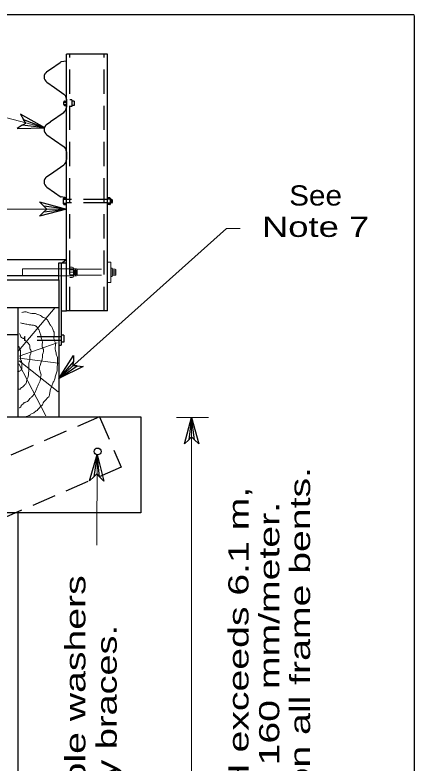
# Model space of a CAD drawing. Extents: x 13426 to 15509, y -9298 to -5111.
# Drawn here: x 15483.31 to 15509.15, y -5428.19 to -5379.81 of the extents above; entities that cross this region are included whole.
import ezdxf
from ezdxf.enums import TextEntityAlignment as Align

# ---------------------------------------------------------------- set-up
doc = ezdxf.new("R2010")
doc.units = 0
doc.header["$LTSCALE"] = 0.52
doc.linetypes.add('MEDIUM_DASHED', pattern=[4.5, 3, -1.5])
for name, color, linetype, lineweight in [('1', 7, 'Continuous', 13), ('15', 7, 'Continuous', 13), ('16', 7, 'Continuous', 25), ('2', 7, 'Continuous', 25), ('20', 7, 'Continuous', 13), ('3', 7, 'Continuous', 25), ('30', 7, 'Continuous', 25), ('4', 7, 'Continuous', 13), ('5', 7, 'Continuous', 25)]:
    doc.layers.add(name, color=color, linetype=linetype, lineweight=lineweight)
doc.layers.add('19', color=7, linetype='Continuous')

msp = doc.modelspace()

# ---------------------------------------------------------------- linework, layer by layer
at = {"layer": '1', "lineweight": 25}
for p, q in [((15485.605, -5383.316), (15486.228, -5382.877)), ((15486.643, -5382.787), (15486.296, -5382.848)), ((15485.375, -5383.473), (15485.603, -5383.314)), ((15485.375, -5384.161), (15485.878, -5384.508)), ((15485.877, -5384.508), (15486.465, -5384.922)), ((15486.643, -5385.768), (15486.643, -5385.265)), ((15486.643, -5385.265), (15486.643, -5385.768)), ((15485.601, -5386.709), (15486.489, -5386.094)), ((15485.375, -5386.873), (15485.603, -5386.713)), ((15485.375, -5387.555), (15485.877, -5387.906)), ((15485.877, -5387.904), (15486.489, -5388.332)), ((15486.643, -5388.656), (15486.643, -5389.155)), ((15486.643, -5389.155), (15486.643, -5388.656)), ((15485.375, -5390.948), (15485.877, -5391.3)), ((15485.877, -5391.299), (15486.228, -5391.548)), ((15486.642, -5391.635), (15486.295, -5391.576)), ((15363.992, -5405.801), (15491.456, -5405.801)), ((15491.456, -5405.801), (15491.456, -5411.997)), ((15491.456, -5411.997), (15381.02, -5411.997)), ((15483.489, -5411.997), (15483.489, -5456.247))]:
    msp.add_line(p, q, dxfattribs=at)
msp.add_lwpolyline([(15485.375, -5390.265), (15485.603, -5390.106), (15486.465, -5389.503)], dxfattribs=at)
for centre, radius, start, end in [((15486.3263, -5383.0135), 0.1669, 100.00085, 124.99926), ((15485.6148, -5383.8174), 0.4173, 124.98392, 235.01553), ((15486.2269, -5385.2642), 0.4173, 359.99953, 55.01553), ((15486.2269, -5385.765), 0.4173, 304.98447, 0.00048), ((15485.6148, -5387.2117), 0.4173, 124.98392, 235.01552), ((15485.6148, -5387.2118), 0.4173, 124.98445, 235.01605), ((15486.2269, -5388.6585), 0.4173, 359.99946, 55.01547), ((15486.2269, -5389.1593), 0.4173, 304.98441, 0.00041), ((15485.6148, -5390.6061), 0.4173, 124.98445, 235.01605), ((15486.324, -5391.4111), 0.1669, 235.00071, 259.99912)]:
    msp.add_arc(centre, radius, start, end, dxfattribs=at)
at = {"layer": '15', "lineweight": 25}
for p, q in [((15486.475, -5385.44), (15486.643, -5385.44)), ((15486.475, -5385.59), (15486.643, -5385.59)), ((15486.519, -5385.378), (15486.643, -5385.378)), ((15486.519, -5385.654), (15486.643, -5385.654))]:
    msp.add_line(p, q, dxfattribs=at)
at = {"layer": '15', "linetype": 'MEDIUM_DASHED', "lineweight": 25}
for p, q in [((15487.138, -5385.378), (15486.996, -5385.378)), ((15487.138, -5385.655), (15486.996, -5385.655))]:
    msp.add_line(p, q, dxfattribs=at)
at = {"layer": '15'}
for p, q in [((15486.643, -5392.358), (15368.805, -5392.358)), ((15496.999, -5393.623), (15486.145, -5403.326)), ((15497.881, -5393.623), (15496.999, -5393.623)), ((15495.847, -5405.842), (15493.759, -5405.842)), ((15494.748, -5405.842), (15494.748, -5464.202)), ((15488.612, -5414.097), (15488.623, -5408.393))]:
    msp.add_line(p, q, dxfattribs=at)
msp.add_lwpolyline([(15485.245, -5387.109), (15480.713, -5385.917), (15478, -5385.917)], dxfattribs=at)
at = {"layer": '16'}
for points in [[(15483.778, -5386.94), (15483.447, -5387.148), (15485.245, -5387.109), (15483.676, -5386.23), (15483.87, -5386.569), (15485.245, -5387.109), (15483.778, -5386.94), (15484.01, -5386.801), (15483.87, -5386.569)], [(15485.178, -5392.166), (15484.908, -5391.885), (15486.643, -5392.358), (15484.908, -5392.831), (15485.178, -5392.55), (15486.643, -5392.358), (15485.178, -5392.166), (15485.37, -5392.358), (15485.178, -5392.55)], [(15487.344, -5402.507), (15487.726, -5402.536), (15486.145, -5403.326), (15487.107, -5401.843), (15487.093, -5402.226), (15486.145, -5403.326), (15487.344, -5402.507), (15487.078, -5402.492), (15487.093, -5402.226)], [(15494.56, -5407.281), (15494.283, -5407.546), (15494.748, -5405.842), (15495.213, -5407.546), (15494.936, -5407.281), (15494.748, -5405.842), (15494.56, -5407.281), (15494.748, -5407.093), (15494.936, -5407.281)], [(15488.41, -5409.67), (15488.127, -5409.929), (15488.63, -5408.236), (15489.057, -5409.95), (15488.786, -5409.678), (15488.63, -5408.236), (15488.41, -5409.67), (15488.602, -5409.486), (15488.786, -5409.678)]]:
    msp.add_lwpolyline(points, dxfattribs=at)
at = {"layer": '2'}
for p, q in [((15486.478, -5400.523), (15486.311, -5400.523)), ((15486.478, -5400.523), (15486.478, -5400.966)), ((15486.478, -5400.966), (15486.311, -5400.966))]:
    msp.add_line(p, q, dxfattribs=at)
at = {"layer": '2', "linetype": 'MEDIUM_DASHED'}
for p, q in [((15486.311, -5400.855), (15483.932, -5400.855)), ((15488.78, -5405.801), (15474.434, -5411.997)), ((15488.78, -5405.801), (15490.184, -5409.051)), ((15490.184, -5409.051), (15478.179, -5414.237))]:
    msp.add_line(p, q, dxfattribs=at)
msp.add_lwpolyline([(15486.311, -5400.634), (15483.932, -5400.634), (15483.932, -5400.855)], dxfattribs=at)
at = {"layer": '2'}
msp.add_circle((15488.6628, -5408.0385), 0.2213, dxfattribs=at)
at = {"layer": '3'}
for p, q in [((15486.475, -5385.61), (15486.475, -5385.422)), ((15486.452, -5392.029), (15486.452, -5391.68)), ((15486.452, -5391.732), (15486.643, -5391.732)), ((15486.496, -5391.636), (15486.642, -5391.636)), ((15489.488, -5391.732), (15489.298, -5391.732)), ((15489.444, -5391.636), (15489.299, -5391.636)), ((15489.488, -5392.029), (15489.488, -5391.68)), ((15489.573, -5391.744), (15489.49, -5391.744)), ((15489.573, -5391.966), (15489.49, -5391.966)), ((15489.517, -5391.776), (15489.517, -5391.936)), ((15489.564, -5391.776), (15489.564, -5391.936)), ((15489.618, -5391.922), (15489.618, -5391.789)), ((15486.452, -5391.981), (15486.643, -5391.981)), ((15486.496, -5392.074), (15486.642, -5392.074)), ((15489.488, -5391.981), (15489.298, -5391.981)), ((15489.444, -5392.074), (15489.299, -5392.074))]:
    msp.add_line(p, q, dxfattribs=at)
at = {"layer": '3', "linetype": 'MEDIUM_DASHED'}
for p, q in [((15486.996, -5385.293), (15486.865, -5385.293)), ((15486.996, -5385.293), (15486.996, -5385.729)), ((15487.138, -5385.378), (15487.138, -5385.655)), ((15486.996, -5385.729), (15486.865, -5385.729)), ((15489.299, -5391.744), (15486.643, -5391.744)), ((15489.299, -5391.966), (15486.643, -5391.966))]:
    msp.add_line(p, q, dxfattribs=at)
at = {"layer": '3'}
for centre, start, end in [((15486.5186, -5385.4222), 90, 180), ((15486.5186, -5385.6102), 180, 270.00003), ((15486.4966, -5391.6801), 90, 180), ((15489.4441, -5391.6801), 0, 90), ((15489.5735, -5391.7886), 0, 90), ((15489.5735, -5391.9214), 270, 0), ((15486.4966, -5392.0293), 180, 269.99999), ((15489.4441, -5392.0293), 270, 0)]:
    msp.add_arc(centre, 0.0443, start, end, dxfattribs=at)
at = {"layer": '30'}
for p, q in [((15509.151, -5379.809), (15181.119, -5379.809)), ((15509.151, -5379.846), (15509.151, -5592.065))]:
    msp.add_line(p, q, dxfattribs=at)
at = {"layer": '4', "lineweight": 25}
for p, q in [((15368.805, -5395.631), (15486.643, -5395.631)), ((15486.643, -5395.631), (15486.377, -5395.843)), ((15486.145, -5396.673), (15479.125, -5396.673)), ((15369.303, -5398.72), (15486.145, -5398.72)), ((15483.49, -5398.72), (15483.49, -5405.801)), ((15483.49, -5400.49), (15478.179, -5400.49))]:
    msp.add_line(p, q, dxfattribs=at)
at = {"layer": '4'}
for p, q in [((15489.52, -5395.789), (15489.299, -5395.789)), ((15489.52, -5395.789), (15489.52, -5397.117)), ((15483.805, -5396.23), (15483.805, -5396.673)), ((15483.805, -5396.23), (15486.643, -5396.23)), ((15487.008, -5396.12), (15486.865, -5396.12)), ((15486.865, -5396.287), (15487.096, -5396.287)), ((15487.096, -5396.694), (15487.096, -5396.209)), ((15487.302, -5396.23), (15487.096, -5396.23)), ((15487.157, -5396.287), (15487.157, -5396.617)), ((15487.221, -5396.23), (15487.221, -5396.673)), ((15487.285, -5396.287), (15487.285, -5396.617)), ((15487.346, -5396.629), (15487.346, -5396.275)), ((15489.603, -5396.176), (15489.52, -5396.176)), ((15489.603, -5396.176), (15489.603, -5396.717)), ((15489.806, -5396.259), (15489.603, -5396.259)), ((15489.851, -5396.602), (15489.851, -5396.303)), ((15486.865, -5396.451), (15487.096, -5396.451)), ((15486.865, -5396.617), (15487.096, -5396.617)), ((15487.008, -5396.782), (15486.865, -5396.782)), ((15487.302, -5396.673), (15487.096, -5396.673)), ((15489.603, -5396.717), (15489.52, -5396.717)), ((15489.603, -5396.356), (15489.851, -5396.356)), ((15489.603, -5396.453), (15489.851, -5396.453)), ((15489.603, -5396.55), (15489.851, -5396.55)), ((15489.806, -5396.646), (15489.603, -5396.646)), ((15489.52, -5397.117), (15489.299, -5397.117)), ((15485.92, -5398.719), (15483.542, -5401.539)), ((15486.052, -5401.013), (15483.575, -5401.879)), ((15486.101, -5402.337), (15483.608, -5402.015)), ((15485.297, -5405.735), (15483.559, -5402.372)), ((15486.101, -5404.172), (15483.575, -5402.168))]:
    msp.add_line(p, q, dxfattribs=at)
at = {"layer": '4', "linetype": 'MEDIUM_DASHED'}
for p, q in [((15487.096, -5396.23), (15486.145, -5396.23)), ((15487.343, -5396.259), (15489.603, -5396.259)), ((15486.145, -5396.673), (15487.096, -5396.673)), ((15487.343, -5396.646), (15489.603, -5396.646))]:
    msp.add_line(p, q, dxfattribs=at)
at = {"layer": '4', "lineweight": 25}
msp.add_lwpolyline([(15369.303, -5396.949), (15486.145, -5396.949), (15486.145, -5405.801)], dxfattribs=at)
at = {"layer": '4'}
for centre, radius, start, end in [((15487.0074, -5396.209), 0.0885, 0.00001, 90), ((15487.3015, -5396.2744), 0.0443, 0.00001, 90), ((15489.8064, -5396.3034), 0.0443, 0.00001, 90), ((15487.0074, -5396.6939), 0.0885, 270, 0), ((15487.3015, -5396.6285), 0.0443, 270, 0), ((15489.8064, -5396.6021), 0.0443, 270, 0)]:
    msp.add_arc(centre, radius, start, end, dxfattribs=at)
for points in [[(15483.755, -5399.059), (15483.985, -5399.008), (15484.198, -5399.076), (15484.608, -5399.109), (15484.641, -5399.109), (15484.723, -5399.161), (15484.969, -5399.245), (15485.068, -5399.33), (15485.133, -5399.382), (15485.15, -5399.382), (15485.412, -5399.534), (15485.477, -5399.636), (15485.609, -5399.874), (15485.674, -5399.942), (15485.756, -5400.129), (15485.855, -5400.401), (15485.855, -5400.503), (15485.838, -5400.791), (15485.92, -5400.979), (15485.937, -5401.149), (15485.92, -5401.284), (15485.904, -5401.335), (15485.904, -5401.386), (15485.92, -5401.454), (15485.937, -5401.539), (15485.97, -5401.658), (15485.986, -5401.743), (15486.035, -5401.896), (15486.068, -5402.032), (15486.068, -5402.151), (15486.068, -5402.337), (15486.052, -5402.542), (15486.035, -5402.83), (15485.953, -5403.085), (15485.888, -5403.34), (15485.79, -5403.561), (15485.691, -5403.799), (15485.609, -5404.019), (15485.56, -5404.274), (15485.494, -5404.495), (15485.379, -5404.614), (15485.248, -5404.767), (15485.133, -5404.886), (15485.117, -5404.954), (15485.084, -5405.022), (15485.018, -5405.09), (15484.92, -5405.192), (15484.838, -5405.277), (15484.74, -5405.379), (15484.641, -5405.447), (15484.526, -5405.549), (15484.346, -5405.634), (15484.28, -5405.685), (15484.198, -5405.719), (15484.116, -5405.753), (15483.968, -5405.804), (15483.967, -5405.804)], [(15483.657, -5399.721), (15483.936, -5399.789), (15484.231, -5399.84), (15484.329, -5399.857), (15484.461, -5399.874), (15484.51, -5399.874), (15484.658, -5399.925), (15484.674, -5399.942), (15484.756, -5400.027), (15484.871, -5400.197), (15484.92, -5400.35), (15484.969, -5400.452), (15484.986, -5400.605), (15485.051, -5400.791), (15485.084, -5400.961), (15485.068, -5401.182), (15485.084, -5401.318), (15485.15, -5401.454), (15485.15, -5401.573), (15485.1, -5401.76), (15485.084, -5401.93), (15484.936, -5402.473), (15484.887, -5402.677), (15484.969, -5402.949), (15485.002, -5403.085), (15484.969, -5403.255), (15484.936, -5403.476), (15484.854, -5403.646), (15484.772, -5403.833), (15484.69, -5404.053), (15484.641, -5404.156), (15484.543, -5404.343), (15484.411, -5404.495), (15484.28, -5404.614), (15484.05, -5404.835), (15483.985, -5404.852), (15483.919, -5404.886), (15483.87, -5404.92), (15483.821, -5404.988), (15483.706, -5405.073), (15483.706, -5405.107), (15483.657, -5405.175), (15483.641, -5405.192), (15483.575, -5405.226)], [(15483.608, -5400.401), (15483.641, -5400.503), (15483.69, -5400.622), (15483.804, -5400.706), (15483.854, -5400.724), (15483.936, -5400.791), (15484.05, -5400.928), (15484.149, -5401.013), (15484.215, -5401.097), (15484.264, -5401.199), (15484.297, -5401.42), (15484.362, -5401.539), (15484.346, -5401.641), (15484.28, -5401.845), (15484.28, -5402.049), (15484.215, -5402.337), (15484.215, -5402.762), (15484.182, -5402.983), (15484.165, -5403.187), (15484.1, -5403.357), (15484.05, -5403.561), (15484.018, -5403.663), (15483.952, -5403.714), (15483.886, -5403.799), (15483.69, -5403.952), (15483.641, -5404.003), (15483.608, -5404.003), (15483.493, -5404.053)], [(15483.559, -5401.233), (15483.608, -5401.352), (15483.624, -5401.42), (15483.657, -5401.488), (15483.657, -5401.556), (15483.673, -5401.624), (15483.673, -5401.675), (15483.673, -5401.743), (15483.657, -5401.913), (15483.673, -5402.066), (15483.722, -5402.202), (15483.755, -5402.355), (15483.755, -5402.661), (15483.739, -5402.728), (15483.722, -5402.728), (15483.69, -5402.796), (15483.591, -5402.847), (15483.525, -5402.881), (15483.477, -5402.915)]]:
    msp.add_spline(points, degree=3, dxfattribs=at)
at = {"layer": '5', "linetype": 'MEDIUM_DASHED'}
for p, q in [((15486.865, -5398.941), (15486.865, -5382.344)), ((15489.077, -5398.941), (15489.077, -5382.344))]:
    msp.add_line(p, q, dxfattribs=at)
at = {"layer": '5'}
for p, q in [((15486.145, -5396.949), (15486.145, -5395.843)), ((15486.311, -5395.843), (15486.311, -5401.154)), ((15489.299, -5398.941), (15486.643, -5398.941)), ((15486.145, -5401.154), (15486.311, -5401.154))]:
    msp.add_line(p, q, dxfattribs=at)
for points in [[(15486.311, -5398.941), (15486.643, -5398.941), (15486.643, -5382.344)], [(15489.299, -5398.941), (15489.299, -5382.344), (15486.643, -5382.344)], [(15486.145, -5395.843), (15486.311, -5395.843), (15486.643, -5395.843)]]:
    msp.add_lwpolyline(points, dxfattribs=at)

# ---------------------------------------------------------------- texts
at = {"layer": '19', "width": 1.45}
for s, p in [('Sway bracing shall be placed on all frame bents.', (15502.418, -5463.422)), ('On frame trestle bents where H exceeds 6.1 m,', (15498.431, -5463.422)), ('outside posts shall be battered 160 mm/meter.', (15500.425, -5463.422))]:
    msp.add_text(s, height=1.307, rotation=90, dxfattribs=at).set_placement(p)
at = {"layer": '19'}
for s, width, p in [('M20 Bolt with malleable washers', 1.45, (15487.869, -5434.4985)), ('at each end of sway braces.', 1.4, (15489.897, -5434.4985))]:
    msp.add_text(s, height=1.307, rotation=90, dxfattribs=dict(at, width=width)).set_placement(p, align=Align.CENTER)
at = {"layer": '20'}
for s, width, p in [('See', 1.1, (15502.7745, -5392.135)), ('Note 7', 1.35, (15502.7745, -5394.163))]:
    msp.add_text(s, height=1.307, dxfattribs=dict(at, width=width)).set_placement(p, align=Align.CENTER)

doc.saveas('drawing.dxf')
